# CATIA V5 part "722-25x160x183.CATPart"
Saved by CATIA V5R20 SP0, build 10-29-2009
Part number: 722-25x160x183
Definition: NONE
Nomenclature: 722-25x160x183
Source: Unknown
Description: 722-25x160x183
Bounding box of the stored display mesh (mm): x -12.5 to 12.5, y -12.5 to 12.5, z -148 to 35
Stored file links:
  C:\Users\Utente\Desktop\IO LAVORO\3D X SITO CF\X SITO\722\722-25x160x183.CATPart
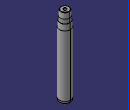
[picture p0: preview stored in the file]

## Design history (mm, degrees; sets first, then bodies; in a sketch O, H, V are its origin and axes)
Body1 "722-25x160x183" (main body)
  Solid1: solid without history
